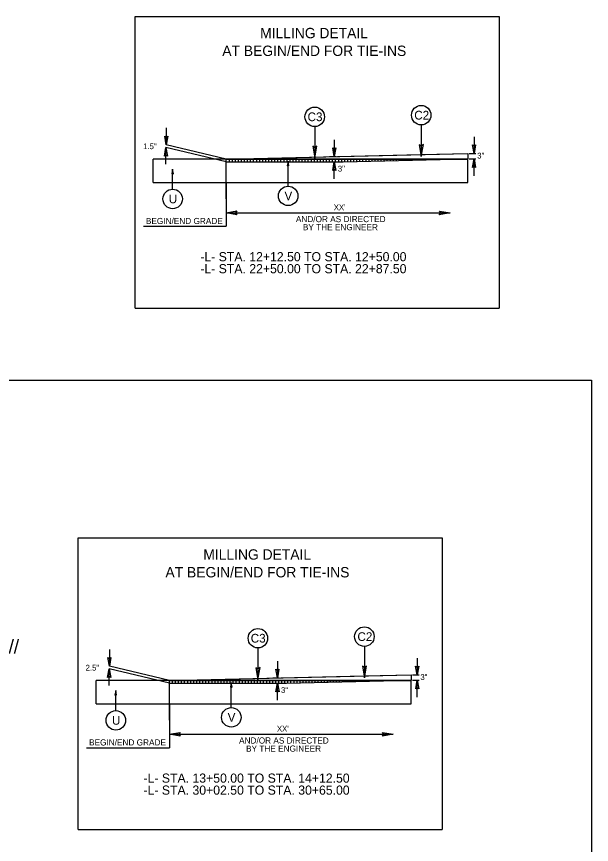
# Model space of a CAD drawing. Extents: x 1548135 to 1549339, y 868664 to 869085.
# Drawn here: x 1548249 to 1548305.7, y 869003.5 to 869085.2 of the extents above; entities that cross this region are included whole.
import ezdxf

# ---------------------------------------------------------------- set-up
doc = ezdxf.new("R2010")
doc.units = 0
for name, color, linetype in [('Default', 7, 'Continuous'), ('P_RDY_DXS_Guardrail_Cell', 7, 'Continuous'), ('Typical Hinge Slope Interstate CELL', 7, 'Continuous')]:
    doc.layers.add(name, color=color, linetype=linetype)

msp = doc.modelspace()

# ---------------------------------------------------------------- linework, layer by layer
at = {"layer": 'Default'}
msp.add_lwpolyline([(1548135.738, 869049.324), (1548305.738, 869049.324), (1548305.738, 868939.324), (1548135.738, 868939.324)], close=True, dxfattribs=at)
at = {"layer": 'P_RDY_DXS_Guardrail_Cell'}
for points in [[(1548288.926, 869071.411), (1548288.963, 869071.619), (1548293.544, 869071.729), (1548293.544, 869071.187), (1548292.285, 869071.157), (1548269.676, 869071.157), (1548288.891, 869071.617)], [(1548283.314, 869019.921), (1548283.351, 869020.128), (1548287.932, 869020.238), (1548287.932, 869019.696), (1548286.672, 869019.666), (1548264.064, 869019.666), (1548283.278, 869020.126)]]:
    msp.add_lwpolyline(points, close=True, dxfattribs=at)
at = {"layer": 'Typical Hinge Slope Interstate CELL'}
for p, q in [((1548263.74, 869074.239), (1548263.74, 869072.566)), ((1548278.409, 869074.376), (1548278.409, 869071.253)), ((1548288.926, 869074.534), (1548288.926, 869071.411)), ((1548294.14, 869073.36), (1548294.141, 869071.717)), ((1548269.676, 869071.157), (1548263.74, 869072.566)), ((1548280.342, 869073.065), (1548280.342, 869071.421)), ((1548269.676, 869070.892), (1548263.718, 869072.306)), ((1548263.718, 869070.663), (1548263.718, 869072.306)), ((1548269.676, 869071.157), (1548293.544, 869071.729)), ((1548293.544, 869071.729), (1548293.544, 869071.187)), ((1548293.673, 869071.717), (1548294.319, 869071.717)), ((1548269.676, 869071.157), (1548262.448, 869071.156)), ((1548262.448, 869068.852), (1548262.448, 869071.156)), ((1548269.676, 869067.235), (1548269.676, 869071.157)), ((1548269.677, 869070.892), (1548269.676, 869071.157)), ((1548269.676, 869071.157), (1548292.285, 869071.157)), ((1548269.676, 869070.892), (1548281.232, 869070.892)), ((1548269.976, 869070.892), (1548269.976, 869071.157)), ((1548270.276, 869070.892), (1548270.276, 869071.157)), ((1548270.576, 869070.892), (1548270.576, 869071.157)), ((1548270.876, 869070.892), (1548270.876, 869071.157)), ((1548271.176, 869070.892), (1548271.176, 869071.157)), ((1548271.476, 869070.892), (1548271.476, 869071.157)), ((1548271.776, 869070.892), (1548271.776, 869071.157)), ((1548272.076, 869070.892), (1548272.076, 869071.157)), ((1548272.376, 869070.892), (1548272.376, 869071.157)), ((1548272.676, 869070.892), (1548272.676, 869071.157)), ((1548272.976, 869070.892), (1548272.976, 869071.157)), ((1548273.276, 869070.892), (1548273.276, 869071.157)), ((1548273.576, 869070.892), (1548273.576, 869071.157)), ((1548273.876, 869070.892), (1548273.876, 869071.157)), ((1548274.176, 869070.892), (1548274.176, 869071.157)), ((1548274.476, 869070.892), (1548274.476, 869071.157)), ((1548274.776, 869070.892), (1548274.776, 869071.157)), ((1548275.076, 869070.892), (1548275.076, 869071.157)), ((1548275.376, 869070.892), (1548275.376, 869071.157)), ((1548275.676, 869070.892), (1548275.676, 869071.157)), ((1548275.783, 869068.487), (1548275.783, 869070.972)), ((1548275.976, 869070.892), (1548275.976, 869071.157)), ((1548276.276, 869070.892), (1548276.276, 869071.157)), ((1548276.576, 869070.892), (1548276.576, 869071.157)), ((1548276.876, 869070.892), (1548276.876, 869071.157)), ((1548277.176, 869070.892), (1548277.176, 869071.157)), ((1548277.476, 869070.892), (1548277.476, 869071.157)), ((1548277.776, 869070.892), (1548277.776, 869071.157)), ((1548278.076, 869070.892), (1548278.076, 869071.157)), ((1548278.376, 869070.892), (1548278.376, 869071.157)), ((1548278.676, 869070.892), (1548278.676, 869071.157)), ((1548278.976, 869070.892), (1548278.976, 869071.157)), ((1548279.276, 869070.892), (1548279.276, 869071.157)), ((1548279.576, 869070.892), (1548279.576, 869071.157)), ((1548279.875, 869071.421), (1548280.52, 869071.421)), ((1548279.875, 869070.892), (1548280.52, 869070.892)), ((1548279.876, 869070.892), (1548279.876, 869071.157)), ((1548280.176, 869070.892), (1548280.176, 869071.157)), ((1548280.341, 869069.218), (1548280.342, 869070.892)), ((1548280.476, 869070.892), (1548280.476, 869071.157)), ((1548280.776, 869070.892), (1548280.776, 869071.157)), ((1548281.076, 869070.892), (1548281.076, 869071.157)), ((1548281.232, 869070.892), (1548293.544, 869071.187)), ((1548281.376, 869070.895), (1548281.376, 869071.157)), ((1548281.676, 869070.902), (1548281.676, 869071.157)), ((1548281.976, 869070.909), (1548281.976, 869071.157)), ((1548282.276, 869070.917), (1548282.276, 869071.157)), ((1548282.576, 869070.924), (1548282.576, 869071.157)), ((1548282.876, 869070.931), (1548282.876, 869071.157)), ((1548283.176, 869070.938), (1548283.176, 869071.157)), ((1548283.476, 869070.945), (1548283.476, 869071.157)), ((1548283.776, 869070.953), (1548283.776, 869071.157)), ((1548284.076, 869070.96), (1548284.076, 869071.157)), ((1548284.376, 869070.967), (1548284.376, 869071.157)), ((1548284.676, 869070.974), (1548284.676, 869071.157)), ((1548284.976, 869070.981), (1548284.976, 869071.157)), ((1548285.276, 869070.989), (1548285.276, 869071.157)), ((1548285.576, 869070.996), (1548285.576, 869071.157)), ((1548285.876, 869071.003), (1548285.876, 869071.157)), ((1548286.176, 869071.01), (1548286.176, 869071.157)), ((1548286.476, 869071.017), (1548286.476, 869071.157)), ((1548286.776, 869071.024), (1548286.776, 869071.157)), ((1548287.076, 869071.032), (1548287.076, 869071.157)), ((1548287.376, 869071.039), (1548287.376, 869071.157)), ((1548287.676, 869071.046), (1548287.676, 869071.157)), ((1548287.976, 869071.053), (1548287.976, 869071.157)), ((1548288.276, 869071.06), (1548288.276, 869071.157)), ((1548288.576, 869071.068), (1548288.576, 869071.157)), ((1548288.876, 869071.075), (1548288.876, 869071.157)), ((1548289.176, 869071.082), (1548289.176, 869071.157)), ((1548289.476, 869071.089), (1548289.476, 869071.157)), ((1548289.776, 869071.096), (1548289.776, 869071.157)), ((1548292.285, 869071.157), (1548293.544, 869071.157)), ((1548293.544, 869068.852), (1548293.544, 869071.157)), ((1548293.673, 869071.187), (1548294.319, 869071.187)), ((1548294.14, 869069.514), (1548294.141, 869071.187)), ((1548264.378, 869068.187), (1548264.378, 869070.183)), ((1548262.448, 869068.852), (1548293.544, 869068.852)), ((1548269.676, 869068.754), (1548269.676, 869065.588)), ((1548269.657, 869065.848), (1548291.784, 869065.849)), ((1548269.676, 869065.588), (1548269.676, 869064.522)), ((1548261.488, 869064.522), (1548269.676, 869064.522)), ((1548260.665, 869056.432), (1548296.62, 869056.432)), ((1548258.128, 869022.748), (1548258.128, 869021.075)), ((1548272.797, 869022.885), (1548272.797, 869019.762)), ((1548283.314, 869023.044), (1548283.314, 869019.921)), ((1548288.528, 869021.87), (1548288.528, 869020.226)), ((1548264.063, 869019.666), (1548258.128, 869021.075)), ((1548274.729, 869021.575), (1548274.729, 869019.931)), ((1548264.064, 869019.401), (1548258.105, 869020.816)), ((1548258.105, 869019.172), (1548258.105, 869020.816)), ((1548264.064, 869019.666), (1548287.932, 869020.238)), ((1548287.932, 869020.238), (1548287.932, 869019.696)), ((1548288.061, 869020.226), (1548288.707, 869020.226)), ((1548264.064, 869019.666), (1548256.835, 869019.666)), ((1548256.835, 869017.361), (1548256.835, 869019.666)), ((1548264.064, 869015.744), (1548264.064, 869019.666)), ((1548264.064, 869019.401), (1548264.064, 869019.666)), ((1548264.064, 869019.666), (1548286.672, 869019.666)), ((1548264.064, 869019.401), (1548275.619, 869019.401)), ((1548264.364, 869019.401), (1548264.364, 869019.666)), ((1548264.664, 869019.401), (1548264.664, 869019.666)), ((1548264.964, 869019.401), (1548264.964, 869019.666)), ((1548265.264, 869019.401), (1548265.264, 869019.666)), ((1548265.564, 869019.401), (1548265.564, 869019.666)), ((1548265.864, 869019.401), (1548265.864, 869019.666)), ((1548266.164, 869019.401), (1548266.164, 869019.666)), ((1548266.464, 869019.401), (1548266.464, 869019.666)), ((1548266.764, 869019.401), (1548266.764, 869019.666)), ((1548267.064, 869019.401), (1548267.064, 869019.666)), ((1548267.364, 869019.401), (1548267.364, 869019.666)), ((1548267.664, 869019.401), (1548267.664, 869019.666)), ((1548267.964, 869019.401), (1548267.964, 869019.666)), ((1548268.264, 869019.401), (1548268.264, 869019.666)), ((1548268.564, 869019.401), (1548268.564, 869019.666)), ((1548268.864, 869019.401), (1548268.864, 869019.666)), ((1548269.164, 869019.401), (1548269.164, 869019.666)), ((1548269.464, 869019.401), (1548269.464, 869019.666)), ((1548269.764, 869019.401), (1548269.764, 869019.666)), ((1548270.064, 869019.401), (1548270.064, 869019.666)), ((1548270.17, 869016.996), (1548270.17, 869019.481)), ((1548270.364, 869019.401), (1548270.364, 869019.666)), ((1548270.664, 869019.401), (1548270.664, 869019.666)), ((1548270.964, 869019.401), (1548270.964, 869019.666)), ((1548271.264, 869019.401), (1548271.264, 869019.666)), ((1548271.564, 869019.401), (1548271.564, 869019.666)), ((1548271.864, 869019.401), (1548271.864, 869019.666)), ((1548272.164, 869019.401), (1548272.164, 869019.666)), ((1548272.464, 869019.401), (1548272.464, 869019.666)), ((1548272.764, 869019.401), (1548272.764, 869019.666)), ((1548273.064, 869019.401), (1548273.064, 869019.666)), ((1548273.364, 869019.401), (1548273.364, 869019.666)), ((1548273.664, 869019.401), (1548273.664, 869019.666)), ((1548273.964, 869019.401), (1548273.964, 869019.666)), ((1548274.262, 869019.931), (1548274.908, 869019.931)), ((1548274.262, 869019.401), (1548274.908, 869019.401)), ((1548274.264, 869019.401), (1548274.264, 869019.666)), ((1548274.564, 869019.401), (1548274.564, 869019.666)), ((1548274.729, 869017.728), (1548274.729, 869019.401)), ((1548274.864, 869019.401), (1548274.864, 869019.666)), ((1548275.164, 869019.401), (1548275.164, 869019.666)), ((1548275.464, 869019.401), (1548275.464, 869019.666)), ((1548275.619, 869019.401), (1548287.932, 869019.696)), ((1548275.764, 869019.404), (1548275.764, 869019.666)), ((1548276.064, 869019.412), (1548276.064, 869019.666)), ((1548276.364, 869019.419), (1548276.364, 869019.666)), ((1548276.664, 869019.426), (1548276.664, 869019.666)), ((1548276.964, 869019.433), (1548276.964, 869019.666)), ((1548277.264, 869019.44), (1548277.264, 869019.666)), ((1548277.564, 869019.448), (1548277.564, 869019.666)), ((1548277.864, 869019.455), (1548277.864, 869019.666)), ((1548278.164, 869019.462), (1548278.164, 869019.666)), ((1548278.464, 869019.469), (1548278.464, 869019.666)), ((1548278.764, 869019.476), (1548278.764, 869019.666)), ((1548279.064, 869019.483), (1548279.064, 869019.666)), ((1548279.364, 869019.491), (1548279.364, 869019.666)), ((1548279.664, 869019.498), (1548279.664, 869019.666)), ((1548279.964, 869019.505), (1548279.964, 869019.666)), ((1548280.264, 869019.512), (1548280.264, 869019.666)), ((1548280.564, 869019.519), (1548280.564, 869019.666)), ((1548280.864, 869019.527), (1548280.864, 869019.666)), ((1548281.164, 869019.534), (1548281.164, 869019.666)), ((1548281.464, 869019.541), (1548281.464, 869019.666)), ((1548281.764, 869019.548), (1548281.764, 869019.666)), ((1548282.064, 869019.555), (1548282.064, 869019.666)), ((1548282.364, 869019.563), (1548282.364, 869019.666)), ((1548282.664, 869019.57), (1548282.664, 869019.666)), ((1548282.964, 869019.577), (1548282.964, 869019.666)), ((1548283.264, 869019.584), (1548283.264, 869019.666)), ((1548283.564, 869019.591), (1548283.564, 869019.666)), ((1548283.864, 869019.599), (1548283.864, 869019.666)), ((1548284.164, 869019.606), (1548284.164, 869019.666)), ((1548286.672, 869019.666), (1548287.932, 869019.666)), ((1548287.932, 869017.361), (1548287.932, 869019.666)), ((1548288.061, 869019.696), (1548288.707, 869019.696)), ((1548288.528, 869018.023), (1548288.528, 869019.696)), ((1548258.766, 869016.697), (1548258.766, 869018.692)), ((1548256.835, 869017.361), (1548287.932, 869017.361)), ((1548264.064, 869017.263), (1548264.064, 869014.097)), ((1548264.044, 869014.358), (1548286.171, 869014.358)), ((1548264.064, 869014.097), (1548264.064, 869013.032)), ((1548255.875, 869013.032), (1548264.064, 869013.032)), ((1548255.052, 869004.942), (1548291.008, 869004.942))]:
    msp.add_line(p, q, dxfattribs=at)
for points in [[(1548260.665, 869056.432), (1548260.665, 869085.237), (1548296.62, 869085.237)], [(1548296.62, 869085.237), (1548296.62, 869056.432)], [(1548255.052, 869004.942), (1548255.052, 869033.746), (1548291.008, 869033.746)], [(1548291.008, 869033.746), (1548291.008, 869004.942)]]:
    msp.add_lwpolyline(points, dxfattribs=at)
for points in [[(1548263.887, 869073.419), (1548263.74, 869072.566), (1548263.589, 869073.424), (1548263.74, 869073.315)], [(1548278.207, 869072.424), (1548278.409, 869071.253), (1548278.617, 869072.431), (1548278.409, 869072.281)], [(1548288.725, 869072.583), (1548288.926, 869071.411), (1548289.135, 869072.589), (1548288.926, 869072.44)], [(1548294.287, 869072.57), (1548294.141, 869071.717), (1548293.989, 869072.575), (1548294.14, 869072.466)], [(1548263.571, 869071.453), (1548263.718, 869072.306), (1548263.87, 869071.448), (1548263.718, 869071.557)], [(1548280.488, 869072.275), (1548280.342, 869071.421), (1548280.19, 869072.279), (1548280.341, 869072.171)], [(1548275.863, 869070.503), (1548275.783, 869070.972), (1548275.699, 869070.501), (1548275.783, 869070.561)], [(1548280.195, 869070.038), (1548280.342, 869070.892), (1548280.493, 869070.034), (1548280.342, 869070.142)], [(1548293.994, 869070.333), (1548294.141, 869071.187), (1548294.292, 869070.329), (1548294.141, 869070.437)], [(1548264.459, 869069.714), (1548264.378, 869070.183), (1548264.295, 869069.712), (1548264.378, 869069.771)], [(1548270.724, 869065.664), (1548269.657, 869065.848), (1548270.73, 869066.038), (1548270.594, 869065.848)], [(1548290.717, 869066.032), (1548291.784, 869065.849), (1548290.711, 869065.659), (1548290.847, 869065.849)], [(1548258.274, 869021.929), (1548258.128, 869021.075), (1548257.976, 869021.933), (1548258.128, 869021.825)], [(1548272.595, 869020.934), (1548272.797, 869019.762), (1548273.005, 869020.94), (1548272.797, 869020.79)], [(1548283.112, 869021.092), (1548283.314, 869019.921), (1548283.522, 869021.099), (1548283.314, 869020.949)], [(1548288.675, 869021.079), (1548288.528, 869020.226), (1548288.376, 869021.084), (1548288.528, 869020.975)], [(1548257.958, 869019.962), (1548258.105, 869020.816), (1548258.257, 869019.958), (1548258.105, 869020.066)], [(1548274.876, 869020.784), (1548274.729, 869019.931), (1548274.577, 869020.789), (1548274.729, 869020.68)], [(1548270.251, 869019.013), (1548270.17, 869019.481), (1548270.087, 869019.01), (1548270.17, 869019.07)], [(1548274.582, 869018.548), (1548274.729, 869019.401), (1548274.881, 869018.543), (1548274.729, 869018.652)], [(1548288.381, 869018.843), (1548288.528, 869019.696), (1548288.68, 869018.838), (1548288.528, 869018.947)], [(1548258.846, 869018.223), (1548258.766, 869018.692), (1548258.682, 869018.221), (1548258.766, 869018.281)], [(1548265.111, 869014.174), (1548264.044, 869014.358), (1548265.117, 869014.547), (1548264.981, 869014.358)], [(1548285.104, 869014.541), (1548286.171, 869014.358), (1548285.099, 869014.168), (1548285.235, 869014.358)]]:
    msp.add_lwpolyline(points, close=True, dxfattribs=at)
for centre in [(1548278.409, 869075.337), (1548288.926, 869075.496), (1548275.783, 869067.525), (1548264.378, 869067.226), (1548272.797, 869023.847), (1548283.314, 869024.005), (1548270.17, 869016.034), (1548258.766, 869015.735)]:
    msp.add_circle(centre, 0.962, dxfattribs=at)

# ---------------------------------------------------------------- texts
for s, height, rotation, p in [('MILLING DETAIL', 1.02324, 359.99993, (1548273.018, 869083.097)), ('1.5"  ', 0.5712, 0.00048, (1548261.461, 869072.142)), ('3"  ', 0.5712, 0.00048, (1548294.458, 869071.218)), ('3"  ', 0.5712, 0.00048, (1548280.692, 869069.931)), ("XX'", 0.5712, 0.00007, (1548280.289, 869066.115)), ('BEGIN/END GRADE', 0.60816, 0.00007, (1548261.736, 869064.745)), ('AND/OR AS DIRECTED', 0.60816, 0.00007, (1548276.55, 869064.933)), ('BY THE ENGINEER', 0.60816, 0.00007, (1548277.24, 869064.136)), ('MILLING DETAIL', 1.02324, 359.99993, (1548267.405, 869031.606)), ('/// ', 1.3568, 358.85371, (1548247.672, 869022.361)), ('2.5"  ', 0.5712, 0.00048, (1548255.78, 869020.651)), ('3"  ', 0.5712, 0.00048, (1548288.845, 869019.727)), ('3"  ', 0.5712, 0.00048, (1548275.08, 869018.441)), ("XX'", 0.5712, 0.00007, (1548274.676, 869014.625)), ('BEGIN/END GRADE', 0.60816, 0.00007, (1548256.123, 869013.255)), ('AND/OR AS DIRECTED', 0.60816, 0.00007, (1548270.937, 869013.443)), ('BY THE ENGINEER', 0.60816, 0.00007, (1548271.627, 869012.645))]:
    msp.add_text(s, height=height, rotation=rotation, dxfattribs=at).set_placement(p)
for s, height, p in [('AT BEGIN/END FOR TIE-INS', 1.02324, (1548269.279, 869081.345)), ('C3', 0.8608, (1548277.702, 869074.907)), ('C2', 0.8608, (1548288.241, 869075.066)), ('U', 0.861, (1548263.996, 869066.795)), ('V', 0.861, (1548275.421, 869067.095)), ('-L- STA. 12+12.50 TO STA. 12+50.00', 0.90387, (1548267.111, 869061.071)), ('-L- STA. 22+50.00 TO STA. 22+87.50', 0.90387, (1548267.111, 869059.886)), ('AT BEGIN/END FOR TIE-INS', 1.02324, (1548263.667, 869029.854)), ('C3', 0.8608, (1548272.089, 869023.416)), ('C2', 0.8608, (1548282.628, 869023.575)), ('U', 0.861, (1548258.383, 869015.305)), ('V', 0.861, (1548269.809, 869015.604)), ('-L- STA. 13+50.00 TO STA. 14+12.50', 0.90387, (1548261.499, 869009.58)), ('-L- STA. 30+02.50 TO STA. 30+65.00', 0.90387, (1548261.499, 869008.396))]:
    msp.add_text(s, height=height, dxfattribs=at).set_placement(p)

doc.saveas('drawing.dxf')
